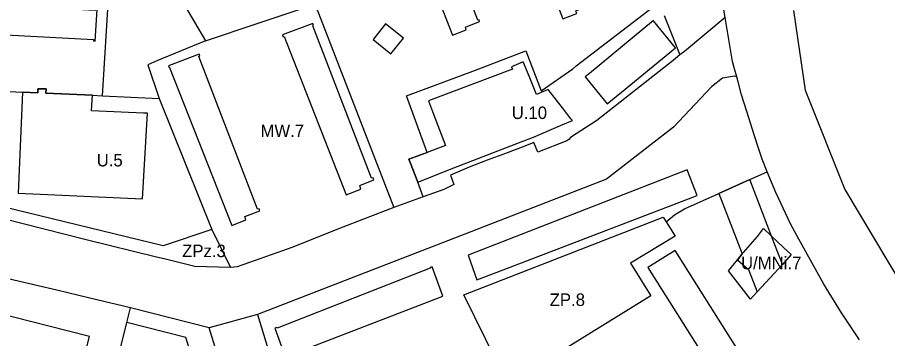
# Model space of a CAD drawing. Extents: x 7425067 to 7426806, y 5549054 to 5550619.
# Drawn here: x 7426010.9 to 7426359, y 5550135 to 5550263.3 of the extents above; entities that cross this region are included whole.
import ezdxf

# ---------------------------------------------------------------- set-up
doc = ezdxf.new("R2010")
doc.units = 0
for name, color, linetype in [('LIN_Linia Zabudowy Nieprzekraczalna', 7, 'Continuous'), ('LIN_linia zabudowy obowiązująca', 7, 'Continuous'), ('LIN_linie_rozgraniczajace', 7, 'Continuous'), ('TXT_Oznaczenia_przeznaczen', 7, 'Continuous')]:
    doc.layers.add(name, color=color, linetype=linetype)

msp = doc.modelspace()

# ---------------------------------------------------------------- linework, layer by layer
at = {"layer": 'LIN_Linia Zabudowy Nieprzekraczalna'}
for points in [[(7426265.3155, 5550262.0006), (7426239.73, 5550240.94), (7426238.0403, 5550239.5491)], [(7426265.4037, 5550261.8926), (7426265.3155, 5550262.0006)], [(7426274.2, 5550251.12), (7426265.4037, 5550261.8926)], [(7426238.0403, 5550239.5491), (7426246.8365, 5550228.7765), (7426252.56, 5550233.45), (7426274.2, 5550251.12)], [(7426213.23, 5550245.49), (7426208.56, 5550243.56), (7426208.9333, 5550242.6599), (7426175.33, 5550230), (7426177.3451, 5550224.6519)], [(7426224.35, 5550218.51), (7426229.03, 5550220.51), (7426232.9016, 5550222.1645), (7426232.34, 5550222.79), (7426229.91, 5550225.99), (7426223.1756, 5550234.4424), (7426218.51, 5550232.44), (7426215.59, 5550239.81), (7426213.23, 5550245.49)], [(7426040.8652, 5550232.1598), (7426022.27, 5550233.04), (7426022.34, 5550234.69), (7426019.1, 5550234.82), (7426019.06, 5550233.19), (7426012.9642, 5550233.4679), (7426011.1692, 5550193.1187)], [(7426062.9127, 5550224.9883), (7426061.37, 5550225.06), (7426040.5299, 5550226.028), (7426040.8652, 5550232.1598)], [(7426060.8701, 5550190.7905), (7426062.9127, 5550224.9883)], [(7426177.3451, 5550224.6519), (7426182.0876, 5550212.0654), (7426174.78, 5550209.37), (7426167.46, 5550206.67), (7426167.99, 5550205.295), (7426171.0262, 5550197.4337), (7426185.4522, 5550203.1356)], [(7426185.4522, 5550203.1356), (7426212.37, 5550213.64), (7426217.3, 5550215.48), (7426224.35, 5550218.51)], [(7426011.1692, 5550193.1187), (7426060.8701, 5550190.7905)], [(7426039.6759, 5550135.8352), (7425961.9593, 5550155.5419)], [(7426078.2794, 5550135.478), (7426054.6154, 5550141.409)], [(7426023.0148, 5550069.5471), (7426039.6759, 5550135.8352)], [(7426088.5093, 5550102.669), (7426078.2794, 5550135.478)]]:
    msp.add_lwpolyline(points, dxfattribs=at)
at = {"layer": 'LIN_linia zabudowy obowiązująca'}
for points in [[(7426229.02, 5550262.72), (7426234.63, 5550264.91), (7426234.28, 5550265.88), (7426239.6, 5550268.12), (7426215.52, 5550330.43), (7426204.64, 5550326.2), (7426229.02, 5550262.72)], [(7426171.46, 5550323.82), (7426171.67, 5550323.97), (7426171.45, 5550324.68), (7426159.59, 5550320.23), (7426159.73, 5550319.53), (7426160.08, 5550319.53), (7426184.94, 5550256.22), (7426190.42, 5550258.35), (7426190.1, 5550259.33), (7426195.78, 5550261.64), (7426195.55, 5550262.29), (7426195.1, 5550262.21), (7426171.46, 5550323.82)], [(7425938.98, 5550271.63), (7425939.01, 5550272.24), (7425938.25, 5550272.28), (7425937.56, 5550259.5), (7425938.5, 5550259.45), (7425938.53, 5550259.97), (7426041.36, 5550254.4), (7426041.33, 5550253.87), (7426042.05, 5550253.83), (7426042.74, 5550266.45), (7426042.01, 5550266.48), (7426041.99, 5550266.06), (7425938.98, 5550271.63)], [(7426152.6, 5550199.03), (7426129.03, 5550259.96), (7426129.28, 5550260.07), (7426129.04, 5550260.83), (7426116.96, 5550256.26), (7426117.19, 5550255.57), (7426117.53, 5550255.65), (7426142.42, 5550192.41), (7426148.24, 5550194.7), (7426147.83, 5550196.09), (7426153.47, 5550198.35), (7426153.2, 5550199.15), (7426152.6, 5550199.03)], [(7426158.12, 5550260.76), (7426153.17, 5550254.42), (7426160.23, 5550248.72), (7426165.28, 5550254.98), (7426158.12, 5550260.76)], [(7426106.91, 5550186.63), (7426083.44, 5550247.66), (7426083.9, 5550247.84), (7426083.63, 5550248.54), (7426071.27, 5550243.91), (7426071.57, 5550243.25), (7426071.79, 5550243.3), (7426096.65, 5550180.2), (7426102.29, 5550182.38), (7426101.86, 5550183.71), (7426107.81, 5550186.08), (7426107.62, 5550186.76), (7426106.91, 5550186.63)], [(7426278.79, 5550202.36), (7426207.56, 5550174.66), (7426191.14, 5550168.28), (7426194.68, 5550158.46), (7426208.01, 5550163.56), (7426282.79, 5550192.18), (7426278.79, 5550202.36)], [(7426303.938, 5550198.4855), (7426291.5012, 5550192.9376)], [(7426316.8871, 5550164.6498), (7426312.562, 5550175.9513), (7426303.938, 5550198.4855)], [(7426291.5012, 5550192.9376), (7426300.8729, 5550168.8347), (7426298.917, 5550166.4446), (7426303.2856, 5550162.6296), (7426306.7883, 5550153.6209), (7426316.8871, 5550164.6498)], [(7426263.03, 5550163.45), (7426311.94, 5550086.1), (7426322.86, 5550093.01), (7426274.07, 5550170.17), (7426263.03, 5550163.45)], [(7426114.75, 5550139.18), (7426114.61, 5550139.48), (7426113.88, 5550139.22), (7426118.19, 5550127.45), (7426118.83, 5550127.68), (7426118.76, 5550127.94), (7426181.12, 5550151.94), (7426176.84, 5550163.62), (7426176.01, 5550163.34), (7426176.01, 5550163.07), (7426114.75, 5550139.18)]]:
    msp.add_lwpolyline(points, dxfattribs=at)
at = {"layer": 'LIN_linie_rozgraniczajace'}
for points in [[(7426044.9249, 5550231.9677), (7426047.44, 5550273.06)], [(7426077.38, 5550268.79), (7426086.09, 5550253.9)], [(7426234.43, 5550243.93), (7426267.52, 5550269.19)], [(7426293.97, 5550263.21), (7426292.49, 5550271.86)], [(7426106.855, 5550260.87), (7426127.62, 5550267.84)], [(7426130.4554, 5550267.4389), (7426161.5, 5550187.3)], [(7426321.38, 5550266.04), (7426325.98, 5550234.23)], [(7426269.5871, 5550264.0774), (7426273.33, 5550254.79)], [(7426293.97, 5550263.21), (7426285.83, 5550256.43)], [(7426296.97, 5550245.7), (7426293.97, 5550263.21)], [(7426086.09, 5550253.9), (7426106.855, 5550260.87)], [(7426273.33, 5550254.79), (7426275.94, 5550248.28)], [(7426285.83, 5550256.43), (7426277.69, 5550249.65)], [(7426086.09, 5550253.9), (7426066.65, 5550245.99)], [(7426193.02, 5550241.79), (7426214.29, 5550249.92)], [(7426214.29, 5550249.92), (7426220.43, 5550234.02)], [(7426275.94, 5550248.28), (7426273.19, 5550246.11)], [(7426277.69, 5550249.65), (7426275.94, 5550248.28)], [(7426066.65, 5550245.99), (7426063.0026, 5550244.4029)], [(7426063.0026, 5550244.4029), (7426067.58, 5550230.9)], [(7426273.19, 5550246.11), (7426242.72, 5550222.05)], [(7426297.77, 5550242.74), (7426296.97, 5550245.7)], [(7426166.59, 5550231.96), (7426193.02, 5550241.79)], [(7426220.43, 5550234.02), (7426233.06, 5550242.74)], [(7426233.06, 5550242.74), (7426234.43, 5550243.93)], [(7426299.17, 5550237.535), (7426298.6354, 5550239.5227), (7426297.77, 5550242.74)], [(7426292.9587, 5550238.9701), (7426288.5548, 5550235.5914)], [(7426297.77, 5550239.82), (7426292.9587, 5550238.9701)], [(7426298.6354, 5550239.5227), (7426297.77, 5550239.82)], [(7426300.57, 5550232.33), (7426299.17, 5550237.535)], [(7426007.59, 5550233.71), (7426012.9642, 5550233.4679), (7426019.06, 5550233.19)], [(7426019.06, 5550233.19), (7426019.1, 5550234.82)], [(7426019.1, 5550234.82), (7426022.34, 5550234.69)], [(7426022.34, 5550234.69), (7426022.27, 5550233.04)], [(7426288.5548, 5550235.5914), (7426273.32, 5550219.44)], [(7426325.98, 5550234.23), (7426341.94, 5550194.61)], [(7426022.27, 5550233.04), (7426040.8652, 5550232.1598), (7426044.9249, 5550231.9677)], [(7426044.9249, 5550231.9677), (7426067.58, 5550230.9)], [(7426067.58, 5550230.9), (7426088.72, 5550178.63)], [(7426174.78, 5550209.37), (7426166.59, 5550231.96)], [(7426302.62, 5550225.73), (7426300.57, 5550232.33)], [(7426305.73, 5550215.92), (7426302.62, 5550225.73)], [(7426242.72, 5550222.05), (7426232.17, 5550215.29)], [(7426273.32, 5550219.44), (7426246.54, 5550198.66)], [(7426217.44, 5550213.29), (7426213.87, 5550211.84)], [(7426219.06, 5550209.5), (7426217.44, 5550213.29)], [(7426230.67, 5550213.98), (7426219.06, 5550209.5)], [(7426231.54, 5550214.57), (7426230.67, 5550213.98)], [(7426232.17, 5550215.29), (7426231.54, 5550214.57)], [(7426307.36, 5550211.01), (7426305.73, 5550215.92)], [(7426167.46, 5550206.67), (7426174.78, 5550209.37)], [(7426213.87, 5550211.84), (7426206.16, 5550208.95)], [(7426308.79, 5550206.69), (7426307.36, 5550211.01)], [(7426167.99, 5550205.295), (7426167.46, 5550206.67)], [(7426198.85, 5550206.21), (7426191.54, 5550203.47)], [(7426206.16, 5550208.95), (7426198.85, 5550206.21)], [(7426314.25, 5550193.36), (7426310.8818, 5550201.5831), (7426308.79, 5550206.69)], [(7426173.26, 5550191.65), (7426171.0262, 5550197.4337), (7426167.99, 5550205.295)], [(7426191.54, 5550203.47), (7426184.09, 5550200.26)], [(7426184.09, 5550200.26), (7426185.52, 5550196.57)], [(7426277.72, 5550186.79), (7426291.5012, 5550192.9376), (7426303.938, 5550198.4855), (7426310.8818, 5550201.5831)], [(7426185.52, 5550196.57), (7426181.49, 5550194.6)], [(7426246.54, 5550198.66), (7426210.79, 5550184.82)], [(7426181.49, 5550194.6), (7426173.26, 5550191.65)], [(7426317.2, 5550187.07), (7426314.25, 5550193.36)], [(7426341.94, 5550194.61), (7426376.27, 5550136.98)], [(7426173.26, 5550191.65), (7426161.5, 5550187.3)], [(7426069.19, 5550172.05), (7426005.08, 5550187.64)], [(7426161.5, 5550187.3), (7426139.28, 5550178.79)], [(7426273.71, 5550184.43), (7426277.72, 5550186.79)], [(7426320.15, 5550180.78), (7426317.2, 5550187.07)], [(7426038.38, 5550174.46), (7426004.8269, 5550182.9338)], [(7426210.79, 5550184.82), (7426180.89, 5550173.295)], [(7426189.52, 5550152.53), (7426269.1832, 5550183.474)], [(7426269.1832, 5550183.474), (7426270.38, 5550181.59)], [(7426270.38, 5550181.59), (7426273.71, 5550184.43)], [(7426270.38, 5550181.59), (7426273.9591, 5550175.9559)], [(7426088.72, 5550178.63), (7426069.19, 5550172.05)], [(7426088.72, 5550178.63), (7426096.1704, 5550163.4048)], [(7426139.28, 5550178.79), (7426131.755, 5550175.785)], [(7426306.9, 5550175.76), (7426309.36, 5550178.96)], [(7426309.36, 5550178.96), (7426309.68, 5550178.66)], [(7426309.68, 5550178.66), (7426312, 5550176.48)], [(7426323.46, 5550174.73), (7426320.15, 5550180.78)], [(7426066.54, 5550167.51), (7426038.38, 5550174.46)], [(7426131.755, 5550175.785), (7426120.6, 5550171.44)], [(7426273.9591, 5550175.9559), (7426256.0858, 5550165.0765)], [(7426301.36, 5550169.43), (7426306.9, 5550175.76)], [(7426312, 5550176.48), (7426312.562, 5550175.9513), (7426317.41, 5550171.39)], [(7426326.77, 5550168.68), (7426323.46, 5550174.73)], [(7426120.6, 5550171.44), (7426116.97, 5550170.1)], [(7426180.89, 5550173.295), (7426152.63, 5550162.35)], [(7426317.41, 5550171.39), (7426320.44, 5550168.53)], [(7426069.59, 5550166.87), (7426066.54, 5550167.51)], [(7426116.97, 5550170.1), (7426107.905, 5550166.89)], [(7426295.37, 5550162.11), (7426298.917, 5550166.4446), (7426300.8729, 5550168.8347), (7426301.36, 5550169.43)], [(7426320.44, 5550168.53), (7426316.8871, 5550164.6498), (7426306.7883, 5550153.6209), (7426305.24, 5550151.93)], [(7426333.43, 5550156.68), (7426326.77, 5550168.68)], [(7426081.91, 5550163.82), (7426069.59, 5550166.87)], [(7426107.905, 5550166.89), (7426098.84, 5550163.68)], [(7426256.0858, 5550165.0765), (7426264.3349, 5550152.0308)], [(7426013.43, 5550157.43), (7425986.58, 5550163.62)], [(7426095.93, 5550163.38), (7426081.91, 5550163.82)], [(7426098.84, 5550163.68), (7426096.1704, 5550163.4048), (7426095.93, 5550163.38)], [(7426152.63, 5550162.35), (7426106.96, 5550144.64)], [(7426304.1, 5550150.69), (7426295.37, 5550162.11)], [(7426026.665, 5550154.29), (7426013.43, 5550157.43)], [(7426039.9, 5550151.15), (7426026.665, 5550154.29)], [(7426340.56, 5550145.33), (7426333.43, 5550156.68)], [(7426056.07, 5550147.23), (7426039.9, 5550151.15)], [(7426211.3674, 5550108.1509), (7426189.52, 5550152.53)], [(7426264.3349, 5550152.0308), (7426228.656, 5550130.0369)], [(7426305.24, 5550151.93), (7426304.1, 5550150.69)], [(7426050.19, 5550123.7), (7426054.6154, 5550141.409), (7426056.07, 5550147.23)], [(7426087.55, 5550139.34), (7426056.07, 5550147.23)], [(7426106.96, 5550144.64), (7426087.55, 5550139.34)], [(7426106.96, 5550144.64), (7426114.165, 5550120.985)], [(7426347.77, 5550134.52), (7426340.56, 5550145.33)], [(7426098.46, 5550104.35), (7426087.55, 5550139.34)]]:
    msp.add_lwpolyline(points, dxfattribs=at)

# ---------------------------------------------------------------- texts
at = {"layer": 'TXT_Oznaczenia_przeznaczen'}
for s, p in [('U.10', (7426208.6281, 5550222.7)), ('MW.7', (7426108.119, 5550215.5058)), ('U.5', (7426042.5984, 5550203.7597)), ('ZPz.3', (7426076.7751, 5550167.5224)), ('U/MNi.7', (7426300.3456, 5550162.6742)), ('ZP.8', (7426223.8165, 5550148.0175))]:
    msp.add_text(s, height=5, dxfattribs=at).set_placement(p)

doc.saveas('drawing.dxf')
